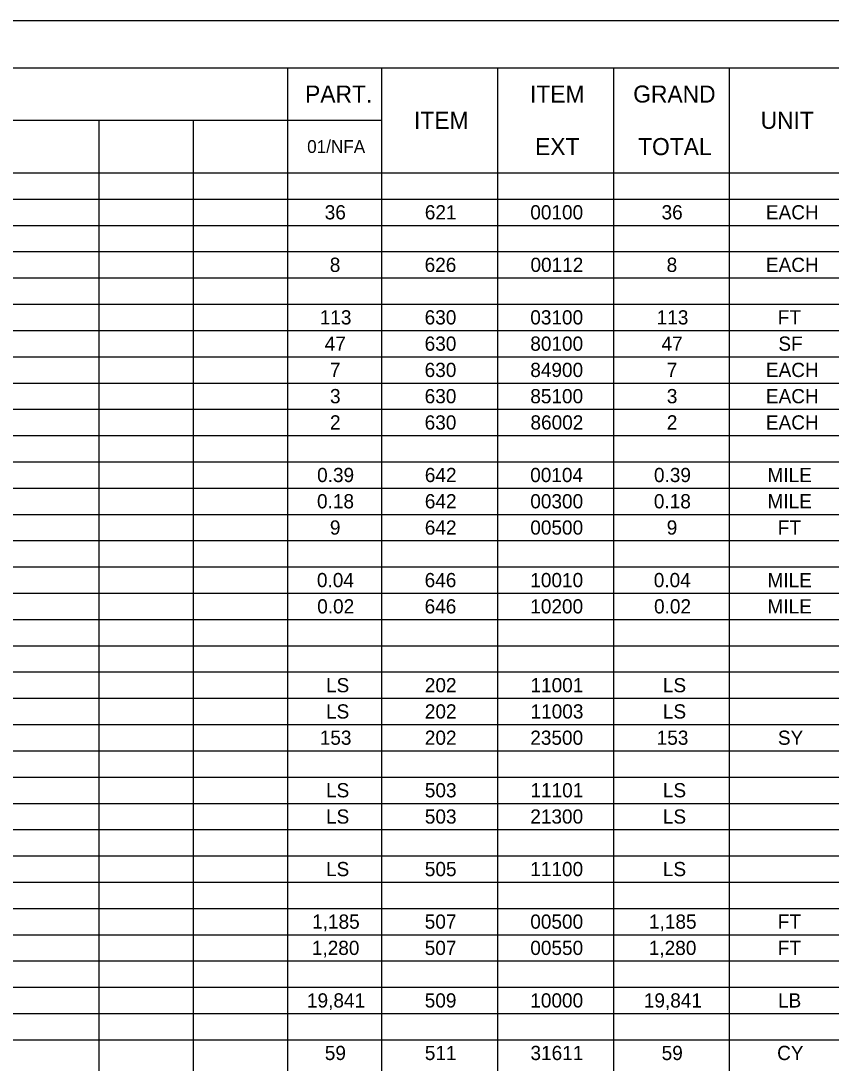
# Model space of a CAD drawing. Extents: x 0 to 34, y 0 to 22.
# Drawn here: x 8.71 to 17.34, y 10.89 to 22 of the extents above; entities that cross this region are included whole.
import ezdxf

# ---------------------------------------------------------------- set-up
doc = ezdxf.new("R2010")
doc.units = 0
for name, color, linetype in [('SH_Border', 7, 'Continuous'), ('SH_Cut_Line', 7, 'Continuous'), ('SH_Text', 7, 'Continuous')]:
    doc.layers.add(name, color=color, linetype=linetype)

msp = doc.modelspace()

# ---------------------------------------------------------------- linework, layer by layer
at = {"layer": 'SH_Border'}
msp.add_lwpolyline([(1.5, 21.5), (33.5, 21.5), (33.5, 0.5), (1.5, 0.5)], close=True, dxfattribs=at)
at = {"layer": 'SH_Cut_Line'}
msp.add_lwpolyline([(0, 0), (34, 0), (34, 22), (0, 22)], close=True, dxfattribs=at)
at = {"layer": 'SH_Text'}
for p, q in [((1.5, 21.5), (32, 21.5)), ((11.546, 21.5), (11.546, 0.5)), ((12.55, 21.5), (12.55, 0.5)), ((13.786, 21.5), (13.786, 0.5)), ((15.021, 21.5), (15.021, 0.5)), ((16.256, 21.5), (16.256, 0.5)), ((1.5, 20.94), (12.55, 20.94)), ((9.537, 20.94), (9.537, 0.5)), ((10.541, 20.94), (10.541, 0.5)), ((1.5, 20.38), (32, 20.38)), ((1.5, 20.1), (32, 20.1)), ((1.5, 19.82), (32, 19.82)), ((1.5, 19.54), (32, 19.54)), ((1.5, 19.26), (32, 19.26)), ((1.5, 18.98), (32, 18.98)), ((1.5, 18.7), (32, 18.7)), ((1.5, 18.42), (32, 18.42)), ((1.5, 18.14), (32, 18.14)), ((1.5, 17.86), (32, 17.86)), ((1.5, 17.58), (32, 17.58)), ((1.5, 17.3), (32, 17.3)), ((1.5, 17.02), (32, 17.02)), ((1.5, 16.74), (32, 16.74)), ((1.5, 16.46), (32, 16.46)), ((1.5, 16.18), (32, 16.18)), ((1.5, 15.9), (32, 15.9)), ((1.5, 15.62), (32, 15.62)), ((1.5, 15.34), (32, 15.34)), ((1.5, 15.06), (32, 15.06)), ((1.5, 14.78), (32, 14.78)), ((1.5, 14.5), (32, 14.5)), ((1.5, 14.22), (32, 14.22)), ((1.5, 13.94), (32, 13.94)), ((1.5, 13.66), (32, 13.66)), ((1.5, 13.38), (32, 13.38)), ((1.5, 13.1), (32, 13.1)), ((1.5, 12.82), (32, 12.82)), ((1.5, 12.54), (32, 12.54)), ((1.5, 12.26), (32, 12.26)), ((1.5, 11.98), (32, 11.98)), ((1.5, 11.7), (32, 11.7)), ((1.5, 11.42), (32, 11.42)), ((1.5, 11.14), (32, 11.14))]:
    msp.add_line(p, q, dxfattribs=at)

# ---------------------------------------------------------------- texts
for s, height, p in [('PART.', 0.1818, (11.735, 21.129)), ('ITEM', 0.1818, (14.132, 21.129)), ('GRAND', 0.1818, (15.232, 21.129)), ('ITEM', 0.1818, (12.896, 20.849)), ('UNIT', 0.1818, (16.59, 20.849)), ('01/NFA', 0.1364, (11.757, 20.592)), ('EXT', 0.1818, (14.186, 20.569)), ('TOTAL', 0.1818, (15.284, 20.569)), ('36', 0.1515, (11.944, 19.884)), ('621', 0.1515, (13.011, 19.884)), ('00100', 0.1515, (14.135, 19.884)), ('36', 0.1515, (15.534, 19.884)), ('EACH', 0.1515, (16.646, 19.884)), ('8', 0.152, (11.998, 19.324)), ('626', 0.1515, (13.009, 19.324)), ('00112', 0.1515, (14.137, 19.324)), ('8', 0.152, (15.588, 19.324)), ('EACH', 0.1515, (16.646, 19.324)), ('113', 0.1515, (11.891, 18.764)), ('630', 0.1515, (13.009, 18.764)), ('03100', 0.1515, (14.135, 18.764)), ('113', 0.1515, (15.482, 18.764)), ('FT', 0.1515, (16.773, 18.764)), ('47', 0.1515, (11.944, 18.484)), ('630', 0.1515, (13.009, 18.484)), ('80100', 0.1515, (14.135, 18.484)), ('47', 0.1515, (15.534, 18.484)), ('SF', 0.1515, (16.779, 18.484)), ('7', 0.152, (11.999, 18.204)), ('630', 0.1515, (13.009, 18.204)), ('84900', 0.1515, (14.135, 18.204)), ('7', 0.152, (15.589, 18.204)), ('EACH', 0.1515, (16.646, 18.204)), ('3', 0.152, (12, 17.924)), ('630', 0.1515, (13.009, 17.924)), ('85100', 0.1515, (14.135, 17.924)), ('3', 0.152, (15.59, 17.924)), ('EACH', 0.1515, (16.646, 17.924)), ('2', 0.152, (12, 17.644)), ('630', 0.1515, (13.009, 17.644)), ('86002', 0.1515, (14.137, 17.644)), ('2', 0.152, (15.59, 17.644)), ('EACH', 0.1515, (16.646, 17.644)), ('0.39', 0.1515, (11.863, 17.084)), ('642', 0.1515, (13.011, 17.084)), ('00104', 0.1515, (14.134, 17.084)), ('0.39', 0.1515, (15.453, 17.084)), ('MILE', 0.1515, (16.663, 17.084)), ('0.18', 0.1515, (11.862, 16.804)), ('642', 0.1515, (13.011, 16.804)), ('00300', 0.1515, (14.135, 16.804)), ('0.18', 0.1515, (15.452, 16.804)), ('MILE', 0.1515, (16.663, 16.804)), ('9', 0.152, (11.999, 16.524)), ('642', 0.1515, (13.011, 16.524)), ('00500', 0.1515, (14.135, 16.524)), ('9', 0.152, (15.589, 16.524)), ('FT', 0.1515, (16.773, 16.524)), ('0.04', 0.1515, (11.861, 15.964)), ('646', 0.1515, (13.009, 15.964)), ('10010', 0.1515, (14.135, 15.964)), ('0.04', 0.1515, (15.451, 15.964)), ('MILE', 0.1515, (16.663, 15.964)), ('0.02', 0.1515, (11.864, 15.684)), ('646', 0.1515, (13.009, 15.684)), ('10200', 0.1515, (14.135, 15.684)), ('0.02', 0.1515, (15.454, 15.684)), ('MILE', 0.1515, (16.663, 15.684)), ('LS', 0.1515, (11.958, 14.844)), ('202', 0.1515, (13.011, 14.844)), ('11001', 0.1515, (14.137, 14.844)), ('LS', 0.1515, (15.548, 14.844)), ('LS', 0.1515, (11.958, 14.564)), ('202', 0.1515, (13.011, 14.564)), ('11003', 0.1515, (14.138, 14.564)), ('LS', 0.1515, (15.548, 14.564)), ('153', 0.1515, (11.891, 14.284)), ('202', 0.1515, (13.011, 14.284)), ('23500', 0.1515, (14.135, 14.284)), ('153', 0.1515, (15.482, 14.284)), ('SY', 0.1515, (16.774, 14.284)), ('LS', 0.1515, (11.958, 13.724)), ('503', 0.1515, (13.011, 13.724)), ('11101', 0.1515, (14.137, 13.724)), ('LS', 0.1515, (15.548, 13.724)), ('LS', 0.1515, (11.958, 13.444)), ('503', 0.1515, (13.011, 13.444)), ('21300', 0.1515, (14.135, 13.444)), ('LS', 0.1515, (15.548, 13.444)), ('LS', 0.1515, (11.958, 12.884)), ('505', 0.1515, (13.011, 12.884)), ('11100', 0.1515, (14.135, 12.884)), ('LS', 0.1515, (15.548, 12.884)), ('1,185', 0.1515, (11.81, 12.324)), ('507', 0.1515, (13.01, 12.324)), ('00500', 0.1515, (14.135, 12.324)), ('1,185', 0.1515, (15.4, 12.324)), ('FT', 0.1515, (16.773, 12.324)), ('1,280', 0.1515, (11.807, 12.044)), ('507', 0.1515, (13.01, 12.044)), ('00550', 0.1515, (14.135, 12.044)), ('1,280', 0.1515, (15.398, 12.044)), ('FT', 0.1515, (16.773, 12.044)), ('19,841', 0.1515, (11.755, 11.484)), ('509', 0.1515, (13.01, 11.484)), ('10000', 0.1515, (14.135, 11.484)), ('19,841', 0.1515, (15.345, 11.484)), ('LB', 0.1515, (16.775, 11.484)), ('59', 0.1515, (11.945, 10.924)), ('511', 0.1515, (13.011, 10.924)), ('31611', 0.1515, (14.137, 10.924)), ('59', 0.1515, (15.535, 10.924)), ('CY', 0.1515, (16.766, 10.924))]:
    msp.add_text(s, height=height, dxfattribs=at).set_placement(p)

doc.saveas('drawing.dxf')
